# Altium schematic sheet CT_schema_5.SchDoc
size 245 x 200 mm
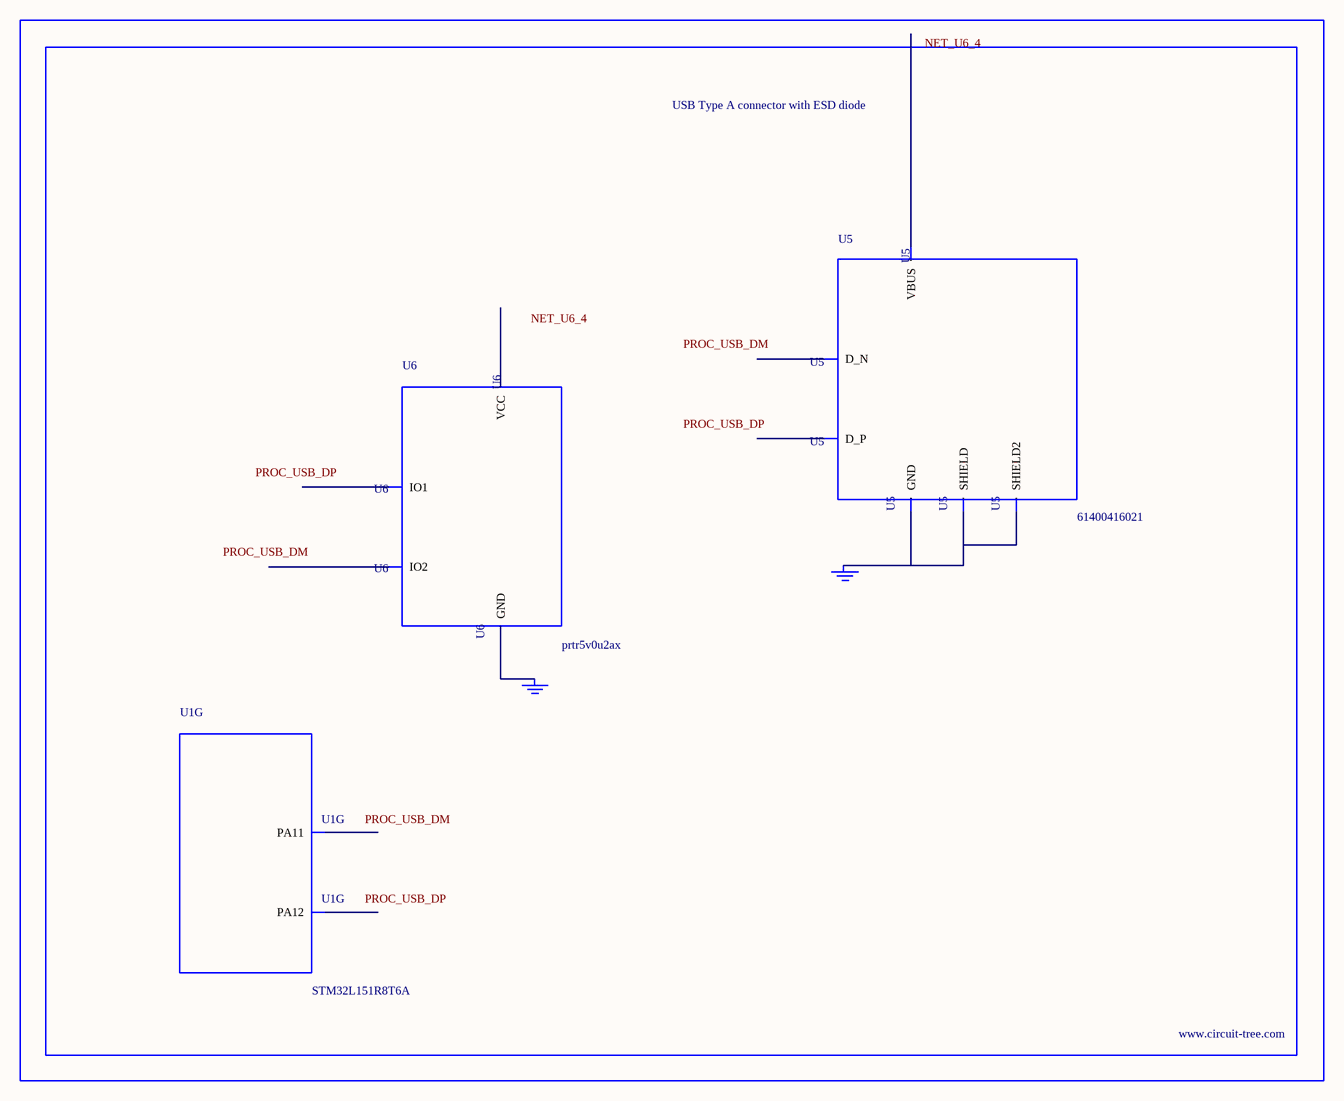
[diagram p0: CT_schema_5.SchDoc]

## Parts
BORDER4  (no value)
GND_INSTANCE_4_0  (no value)
GND_INSTANCE_4_1  (no value)
U1  STM32L151R8T6A  [LQFP64]  (part G of 7)
U5  61400416021  [USB-A-H]
U6  prtr5v0u2ax  [SOT143B]

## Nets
NetGND_INSTANCE_4_0_0: GND_INSTANCE_4_0.0(GND) U5.4(GND) U5.5(SHIELD) U5.6(SHIELD2)
NetGND_INSTANCE_4_1_0: GND_INSTANCE_4_1.0(GND) U6.1(GND)

Not connected (* = marked no-connect by the designer): U1 44(PA11) 45(PA12); U5 1(VBUS) 2(D_N) 3(D_P); U6 2(IO1) 3(IO2) 4(VCC)

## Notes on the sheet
- Labels drawn without touching a wire or pin: NET_U6_4, PROC_USB_DM, PROC_USB_DP

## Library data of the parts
BORDER4 = BORDER_PAGE4
GND_INSTANCE_4_0 GND_INSTANCE_4_1 = GND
